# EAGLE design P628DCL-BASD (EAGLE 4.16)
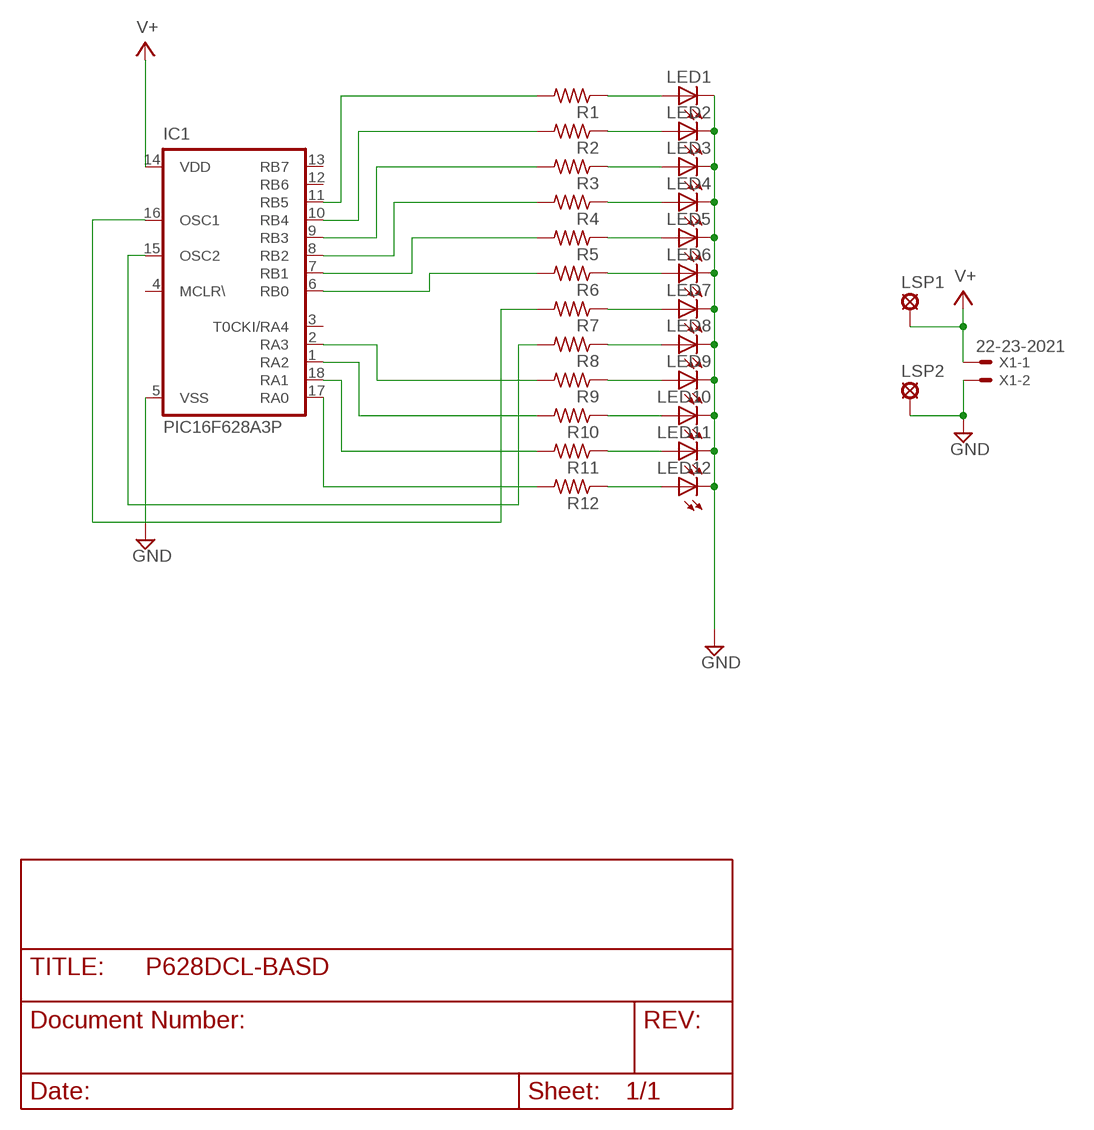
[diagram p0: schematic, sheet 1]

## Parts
IC1  PIC16F628A3P  [DIL18]
LED1  LEDLZR181  [LZR181]
LED2  LEDLZR181  [LZR181]
LED3  LEDLZR181  [LZR181]
LED4  LEDLZR181  [LZR181]
LED5  LEDLZR181  [LZR181]
LED6  LEDLZR181  [LZR181]
LED7  LEDLZR181  [LZR181]
LED8  LEDLZR181  [LZR181]
LED9  LEDLZR181  [LZR181]
LED10  LEDLZR181  [LZR181]
LED11  LEDLZR181  [LZR181]
LED12  LEDLZR181  [LZR181]
LSP1  LSP10  [LSP10]
LSP2  LSP10  [LSP10]
R1  R-US_0207/10  [0207/10]
R2  R-US_0207/10  [0207/10]
R3  R-US_0207/10  [0207/10]
R4  R-US_0207/10  [0207/10]
R5  R-US_0207/10  [0207/10]
R6  R-US_0207/10  [0207/10]
R7  R-US_0207/10  [0207/10]
R8  R-US_0207/10  [0207/10]
R9  R-US_0207/10  [0207/10]
R10  R-US_0207/10  [0207/10]
R11  R-US_0207/10  [0207/10]
R12  R-US_0207/10  [0207/10]
X1  22-23-2021  [22-23-2021]

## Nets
GND: IC1.5(VSS) LED1.K(C) LED2.K(C) LED3.K(C) LED4.K(C) LED5.K(C) LED6.K(C) LED7.K(C) LED8.K(C) LED9.K(C) LED10.K(C) LED11.K(C) LED12.K(C) LSP2.MP X1.2
N$1: IC1.16(OSC1) R7.2
N$2: LED1.A R1.1
N$3: LED2.A R2.1
N$4: LED3.A R3.1
N$5: LED4.A R4.1
N$6: LED5.A R5.1
N$7: LED6.A R6.1
N$8: LED7.A R7.1
N$9: LED8.A R8.1
N$10: LED9.A R9.1
N$11: LED10.A R10.1
N$12: LED11.A R11.1
N$13: LED12.A R12.1
N$14: IC1.15(OSC2) R8.2
N$17: IC1.17(RA0) R12.2
N$18: IC1.18(RA1) R11.2
N$19: IC1.1(RA2) R10.2
N$20: IC1.2(RA3) R9.2
N$22: IC1.10(RB4) R2.2
N$23: IC1.9(RB3) R3.2
N$24: IC1.8(RB2) R4.2
N$25: IC1.7(RB1) R5.2
N$26: IC1.6(RB0) R6.2
N$29: IC1.11(RB5) R1.2
V+: IC1.14(VDD) LSP1.MP X1.1
Unconnected: IC1.3(T0CKI/RA4) IC1.4(MCLR\) IC1.12(RB6) IC1.13(RB7)

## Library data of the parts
IC1 = microchip:PIC16F628A: MICROCONTROLLER 8-Bit PIC16F8X Family - CMOS Flash/EEPROM Pin Compatible : PIC16F83, PIC16CR83, PIC16F84A, PIC16CR84 see also PIC16C*
LED1-LED12 = led:LED: LED
LSP1 LSP2 = solpad:LSP10: SOLDER PAD
R1-R12 = rcl:R-US_: RESISTOR, American symbol
X1 = con-molex:22-23-2021: .100" (2.54mm) Center Header - 2 Pin

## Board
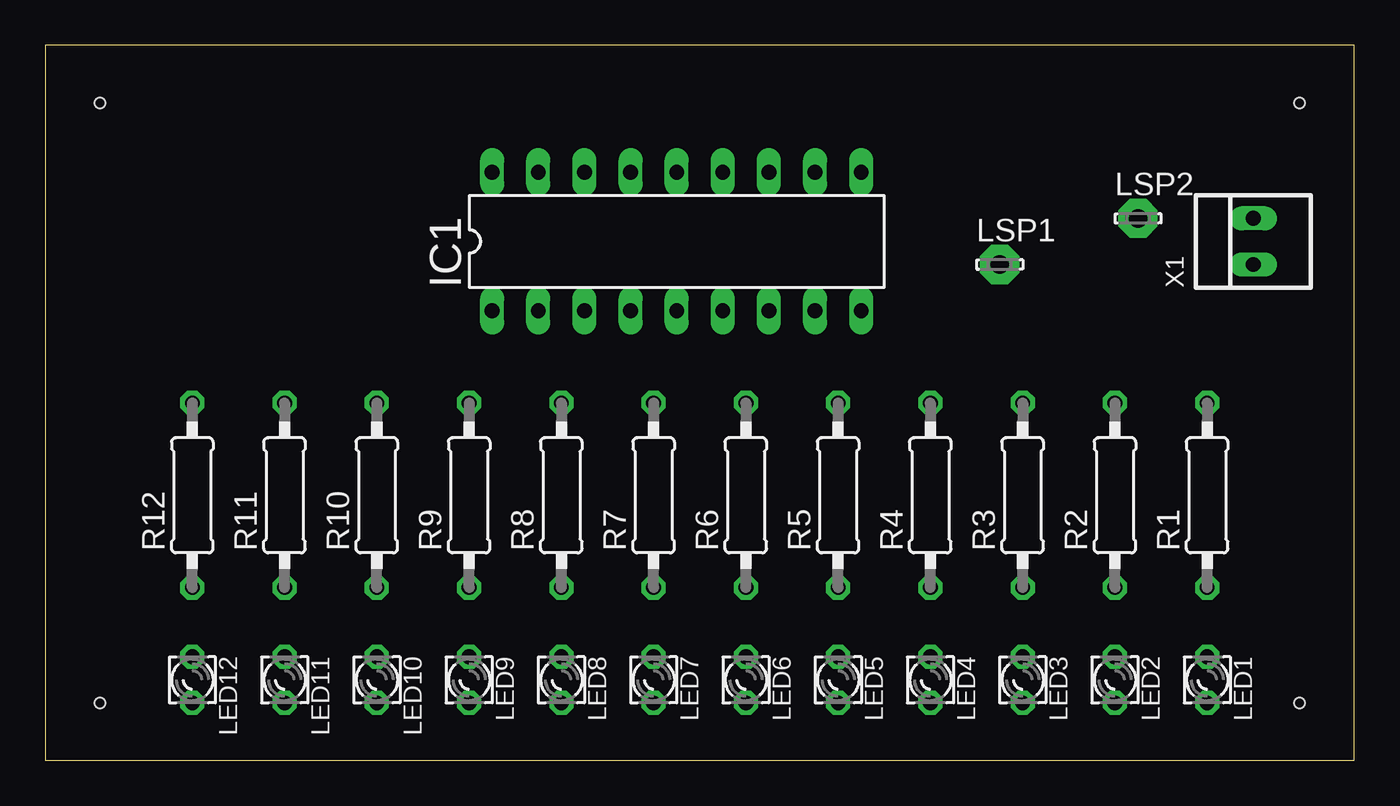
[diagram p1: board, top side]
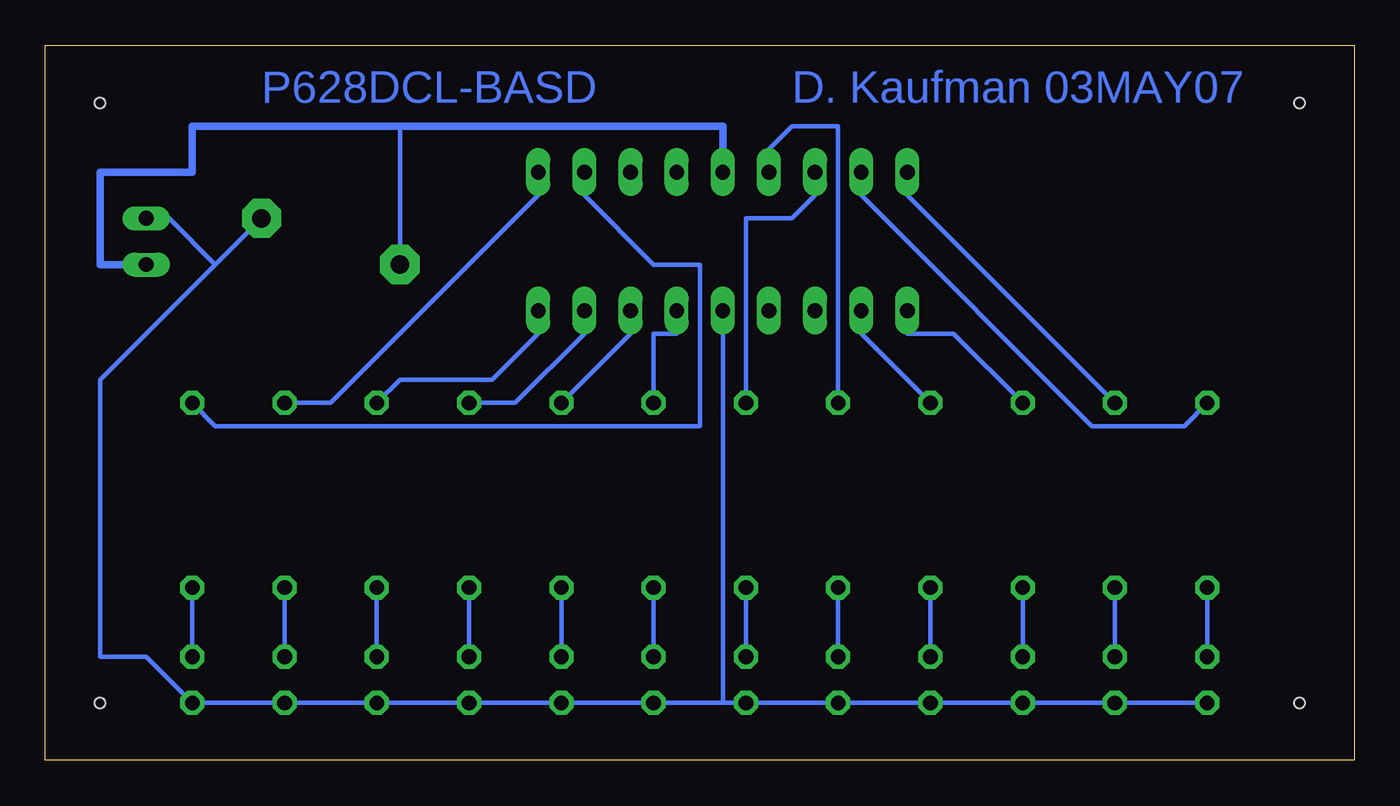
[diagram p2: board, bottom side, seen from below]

Size 72.06 x 39.36 mm. Coordinates in mm from the lower left corner, seen from the top.
Outline: 0,0 72.06,0 72.06,39.36 0,39.36 0,0
Copper layers (1*16): Top 0.035mm / dielectric 1.5mm / Bottom 0.035mm
Design rules "default": minimum track width 10mil, minimum drill 24mil, track to track 8mil, track to pad 8mil, pad to pad 8mil, via to via 8mil, smd to smd 8mil, copper to edge 40mil, drill to drill 8mil, minimum pad ring 10mil, minimum via ring 8mil, stop-mask expansion 4mil, vias tented up to drill 0mil, thermal gap 10mil
Holes 0.6 mm at 3.01,3.17 69.05,3.17 3.01,36.19 69.05,36.19

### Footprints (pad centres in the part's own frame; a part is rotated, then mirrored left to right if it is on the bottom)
DIL18 = drill 0.813 long: 1 -10.16,-3.81; 2 -7.62,-3.81; 3 -5.08,-3.81; 4 -2.54,-3.81; 5 0,-3.81; 6 2.54,-3.81; 7 5.08,-3.81; 8 7.62,-3.81; 9 10.16,-3.81; 10 10.16,3.81; 11 7.62,3.81; 12 5.08,3.81; 13 2.54,3.81; 14 0,3.81; 15 -2.54,3.81; 16 -5.08,3.81; 17 -7.62,3.81; 18 -10.16,3.81
LZR181 = drill 0.813 octagon: A -1.27,0; K 1.27,0
LSP10 = drill 1.016 pad 2.159 octagon: MP 0,0
0207/10 = drill 0.813 octagon: 1 -5.08,0; 2 5.08,0
22-23-2021 = drill 0.813 long: 1 -1.27,0; 2 1.27,0

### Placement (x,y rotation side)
IC1  34.76,28.57 0 top
LED1  63.97,4.44 270 top
LED2  58.89,4.44 270 top
LED3  53.81,4.44 270 top
LED4  48.73,4.44 270 top
LED5  43.65,4.44 270 top
LED6  38.57,4.44 270 top
LED7  33.49,4.44 270 top
LED8  28.41,4.44 270 top
LED9  23.33,4.44 270 top
LED10  18.25,4.44 270 top
LED11  13.17,4.44 270 top
LED12  8.09,4.44 270 top
LSP1  52.54,27.3 0 top
LSP2  60.16,29.84 0 top
R1  63.97,14.6 90 top
R2  58.89,14.6 90 top
R3  53.81,14.6 90 top
R4  48.73,14.6 90 top
R5  43.65,14.6 90 top
R6  38.57,14.6 90 top
R7  33.49,14.6 90 top
R8  28.41,14.6 90 top
R9  23.33,14.6 90 top
R10  18.25,14.6 90 top
R11  13.17,14.6 90 top
R12  8.09,14.6 90 top
X1  66.51,28.57 90 top

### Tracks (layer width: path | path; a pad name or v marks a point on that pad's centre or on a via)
GND
  Bottom 0.254: LED12.K LED11.K LED10.K LED9.K LED8.K LED7.K 34.76,3.17 | 34.76,3.17 LED6.K LED5.K LED4.K LED3.K LED2.K LED1.K 66.51,5.71 69.05,5.71 69.05,20.95 62.7,27.3 | 34.76,3.17 IC1.5 | 62.7,27.3 65.24,29.84 X1.2 | 62.7,27.3 LSP2.MP
N$1
  Bottom 0.254: R7.2 33.49,29.84 30.95,29.84 29.68,31.11 IC1.16
N$2
  Bottom 0.254: LED1.A R1.1
N$3
  Bottom 0.254: LED2.A R2.1
N$4
  Bottom 0.254: LED3.A R3.1
N$5
  Bottom 0.254: LED4.A R4.1
N$6
  Bottom 0.254: LED5.A R5.1
N$7
  Bottom 0.254: LED6.A R6.1
N$8
  Bottom 0.254: LED7.A R7.1
N$9
  Bottom 0.254: LED8.A R8.1
N$10
  Bottom 0.254: LED9.A R9.1
N$11
  Bottom 0.254: LED10.A R10.1
N$12
  Bottom 0.254: LED11.A R11.1
N$13
  Bottom 0.254: LED12.A R12.1
N$14
  Bottom 0.254: R8.2 28.41,34.92 30.95,34.92 32.22,33.65 IC1.15
N$17
  Bottom 0.254: R12.2 9.36,18.41 14.44,18.41 27.14,31.11 IC1.17
N$18
  Bottom 0.254: R11.2 24.6,31.11 IC1.18
N$19
  Bottom 0.254: R10.2 22.06,23.49 24.6,23.49 IC1.1
N$20
  Bottom 0.254: R9.2 27.14,23.49 IC1.2
N$22
  Bottom 0.254: R2.2 56.35,19.68 44.92,31.11 IC1.10
N$23
  Bottom 0.254: R3.2 52.54,20.95 47.46,20.95 44.92,23.49 IC1.9
N$24
  Bottom 0.254: R4.2 46.19,19.68 42.38,23.49 IC1.8
N$25
  Bottom 0.254: R5.2 39.84,23.49 IC1.7
N$26
  Bottom 0.254: R6.2 38.57,23.49 37.3,23.49 IC1.6
N$29
  Bottom 0.254: R1.2 62.7,18.41 36.03,18.41 36.03,27.3 38.57,27.3 42.38,31.11 IC1.11
V+
  Bottom 0.254: 52.54,34.92 LSP1.MP
  Bottom 0.406: X1.1 69.05,27.3 69.05,32.38 63.97,32.38 63.97,34.92 52.54,34.92 34.76,34.92 IC1.14

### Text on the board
Bottom: D. Kaufman 03MAY07 | P628DCL-BASD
